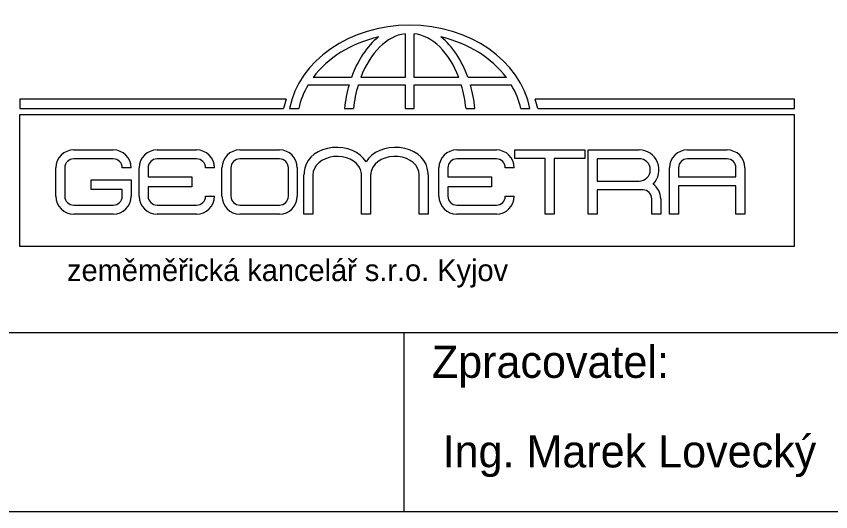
# Model space of a CAD drawing. Extents: x -558358 to -557517, y -1073785 to -1073189.
# Drawn here: x -557597.85 to -557552.36, y -1073682.09 to -1073654.43 of the extents above; entities that cross this region are included whole.
import ezdxf

# ---------------------------------------------------------------- set-up
doc = ezdxf.new("R2010")
doc.units = 0
doc.layers.add('Rozpiska_pole_6', color=7, linetype='Continuous')
doc.layers.add('ZZZ - Razítko', color=7, linetype='Continuous')

msp = doc.modelspace()

# ---------------------------------------------------------------- linework, layer by layer
at = {"layer": 'Rozpiska_pole_6'}
for p, q in [((-557706.534, -1073672.088), (-557536.534, -1073672.088)), ((-557576.184, -1073682.088), (-557576.184, -1073672.088))]:
    msp.add_line(p, q, dxfattribs=at)
msp.add_lwpolyline([(-557706.534, -1073632.088), (-557536.534, -1073632.088), (-557536.534, -1073682.088), (-557706.534, -1073682.088)], close=True, dxfattribs=at)
at = {"layer": 'ZZZ - Razítko'}
for p, q in [((-557576.139, -1073655.401), (-557576.139, -1073657.847)), ((-557575.632, -1073657.847), (-557575.632, -1073655.399)), ((-557579.132, -1073657.847), (-557581.277, -1073657.847)), ((-557576.139, -1073657.847), (-557578.615, -1073657.847)), ((-557573.137, -1073657.847), (-557575.632, -1073657.847)), ((-557570.475, -1073657.847), (-557572.62, -1073657.847)), ((-557581.552, -1073658.258), (-557579.265, -1073658.258)), ((-557578.755, -1073658.258), (-557576.139, -1073658.258)), ((-557576.139, -1073658.258), (-557576.139, -1073659.578)), ((-557575.632, -1073659.578), (-557575.632, -1073658.258)), ((-557575.632, -1073658.258), (-557572.998, -1073658.258)), ((-557572.488, -1073658.258), (-557570.2, -1073658.258)), ((-557582.783, -1073659.047), (-557597.663, -1073659.047)), ((-557597.663, -1073659.047), (-557597.663, -1073659.578)), ((-557554.385, -1073659.047), (-557568.863, -1073659.047)), ((-557554.385, -1073659.578), (-557554.385, -1073659.047)), ((-557597.663, -1073659.578), (-557582.921, -1073659.578)), ((-557582.595, -1073659.578), (-557582.078, -1073659.578)), ((-557579.522, -1073659.578), (-557579.022, -1073659.578)), ((-557576.139, -1073659.578), (-557575.632, -1073659.578)), ((-557572.731, -1073659.578), (-557572.23, -1073659.578)), ((-557569.674, -1073659.578), (-557569.157, -1073659.578)), ((-557568.725, -1073659.578), (-557554.385, -1073659.578)), ((-557554.387, -1073659.923), (-557597.67, -1073659.923)), ((-557597.67, -1073659.923), (-557597.67, -1073667.261)), ((-557554.387, -1073667.261), (-557554.387, -1073659.923)), ((-557594.645, -1073661.889), (-557592.434, -1073661.889)), ((-557589.989, -1073661.889), (-557587.778, -1073661.889)), ((-557585.365, -1073661.889), (-557583.154, -1073661.889)), ((-557573.246, -1073661.889), (-557571.036, -1073661.889)), ((-557565.909, -1073661.889), (-557563.064, -1073661.889)), ((-557560.361, -1073661.889), (-557558.15, -1073661.889)), ((-557592.434, -1073662.387), (-557594.645, -1073662.387)), ((-557587.778, -1073662.387), (-557589.989, -1073662.387)), ((-557583.154, -1073662.387), (-557585.365, -1073662.387)), ((-557571.036, -1073662.387), (-557573.246, -1073662.387)), ((-557568.303, -1073665.471), (-557568.303, -1073662.375)), ((-557567.8, -1073662.375), (-557567.8, -1073665.471)), ((-557563.064, -1073662.378), (-557565.405, -1073662.378)), ((-557565.405, -1073662.378), (-557565.405, -1073663.627)), ((-557558.15, -1073662.387), (-557560.361, -1073662.387)), ((-557595.643, -1073664.473), (-557595.643, -1073662.887)), ((-557595.144, -1073662.887), (-557595.144, -1073664.473)), ((-557591.437, -1073662.887), (-557591.935, -1073662.887)), ((-557590.986, -1073664.473), (-557590.986, -1073662.887)), ((-557590.488, -1073662.887), (-557590.488, -1073663.397)), ((-557586.78, -1073662.887), (-557587.279, -1073662.887)), ((-557586.363, -1073664.473), (-557586.363, -1073662.887)), ((-557585.864, -1073662.887), (-557585.864, -1073664.473)), ((-557582.655, -1073664.473), (-557582.655, -1073662.887)), ((-557582.156, -1073662.887), (-557582.156, -1073664.473)), ((-557574.244, -1073664.473), (-557574.244, -1073662.887)), ((-557573.745, -1073662.887), (-557573.745, -1073663.397)), ((-557570.038, -1073662.887), (-557570.536, -1073662.887)), ((-557561.359, -1073665.471), (-557561.359, -1073662.887)), ((-557560.86, -1073662.887), (-557560.86, -1073663.395)), ((-557557.651, -1073663.395), (-557557.651, -1073662.887)), ((-557557.152, -1073662.887), (-557557.152, -1073665.471)), ((-557581.784, -1073665.471), (-557581.784, -1073663.286)), ((-557581.283, -1073663.286), (-557581.283, -1073665.471)), ((-557578.564, -1073665.471), (-557578.564, -1073663.286)), ((-557578.063, -1073663.286), (-557578.063, -1073665.471)), ((-557575.345, -1073665.471), (-557575.345, -1073663.286)), ((-557574.844, -1073663.286), (-557574.844, -1073665.471)), ((-557593.67, -1073664.095), (-557593.67, -1073663.55)), ((-557593.67, -1073663.55), (-557591.437, -1073663.55)), ((-557591.437, -1073663.55), (-557591.437, -1073664.473)), ((-557590.488, -1073663.397), (-557588.045, -1073663.397)), ((-557588.045, -1073663.397), (-557588.045, -1073663.942)), ((-557573.745, -1073663.397), (-557571.302, -1073663.397)), ((-557571.302, -1073663.397), (-557571.302, -1073663.942)), ((-557565.405, -1073663.627), (-557563.064, -1073663.627)), ((-557560.86, -1073663.395), (-557557.651, -1073663.395)), ((-557591.935, -1073664.095), (-557593.67, -1073664.095)), ((-557591.935, -1073664.473), (-557591.935, -1073664.095)), ((-557588.045, -1073663.942), (-557590.488, -1073663.942)), ((-557590.488, -1073663.942), (-557590.488, -1073664.473)), ((-557571.302, -1073663.942), (-557573.745, -1073663.942)), ((-557573.745, -1073663.942), (-557573.745, -1073664.473)), ((-557563.064, -1073664.116), (-557565.405, -1073664.116)), ((-557562.85, -1073664.12), (-557563.064, -1073664.116)), ((-557557.651, -1073663.899), (-557560.86, -1073663.899)), ((-557560.86, -1073663.899), (-557560.86, -1073665.471)), ((-557557.651, -1073665.471), (-557557.651, -1073663.899)), ((-557587.279, -1073664.473), (-557586.78, -1073664.473)), ((-557570.536, -1073664.473), (-557570.038, -1073664.473)), ((-557562.351, -1073665.471), (-557562.351, -1073664.619)), ((-557561.853, -1073664.619), (-557561.853, -1073665.471)), ((-557594.645, -1073664.972), (-557592.434, -1073664.972)), ((-557589.989, -1073664.972), (-557587.778, -1073664.972)), ((-557585.365, -1073664.972), (-557583.154, -1073664.972)), ((-557573.246, -1073664.972), (-557571.036, -1073664.972)), ((-557592.434, -1073665.471), (-557594.645, -1073665.471)), ((-557587.778, -1073665.471), (-557589.989, -1073665.471)), ((-557583.154, -1073665.471), (-557585.365, -1073665.471)), ((-557581.283, -1073665.471), (-557581.784, -1073665.471)), ((-557578.063, -1073665.471), (-557578.564, -1073665.471)), ((-557574.844, -1073665.471), (-557575.345, -1073665.471)), ((-557571.036, -1073665.471), (-557573.246, -1073665.471)), ((-557567.8, -1073665.471), (-557568.303, -1073665.471)), ((-557561.853, -1073665.471), (-557562.351, -1073665.471)), ((-557560.86, -1073665.471), (-557561.359, -1073665.471)), ((-557557.152, -1073665.471), (-557557.651, -1073665.471)), ((-557597.67, -1073667.261), (-557554.387, -1073667.261))]:
    msp.add_line(p, q, dxfattribs=at)
for points in [[(-557568.303, -1073662.375), (-557570.001, -1073662.375), (-557570.001, -1073661.889), (-557566.087, -1073661.889)], [(-557566.087, -1073661.889), (-557566.087, -1073662.375), (-557567.8, -1073662.375)], [(-557565.405, -1073664.116), (-557565.405, -1073665.471), (-557565.909, -1073665.471), (-557565.909, -1073661.889)]]:
    msp.add_lwpolyline(points, dxfattribs=at)
for centre, radius, start, end in [((-557594.645, -1073662.887), 0.998, 90, 180), ((-557592.434, -1073662.887), 0.998, 360, 90), ((-557589.989, -1073662.887), 0.998, 90, 180), ((-557587.778, -1073662.887), 0.998, 360, 90), ((-557585.365, -1073662.887), 0.998, 90, 180), ((-557583.154, -1073662.887), 0.998, 360, 90), ((-557573.246, -1073662.887), 0.998, 90, 180), ((-557571.036, -1073662.887), 0.998, 360, 90), ((-557563.064, -1073663.003), 1.114, 314.4573, 90), ((-557560.361, -1073662.887), 0.998, 90, 180), ((-557558.15, -1073662.887), 0.998, 360, 90), ((-557594.645, -1073662.887), 0.499, 90, 180), ((-557592.434, -1073662.887), 0.499, 0, 90), ((-557589.989, -1073662.887), 0.499, 90, 180), ((-557587.778, -1073662.887), 0.499, 0, 90), ((-557585.365, -1073662.887), 0.499, 90, 180), ((-557583.154, -1073662.887), 0.499, 0, 90), ((-557573.246, -1073662.887), 0.499, 90, 180), ((-557571.036, -1073662.887), 0.499, 0, 90), ((-557563.064, -1073663.003), 0.625, 270, 90), ((-557560.361, -1073662.887), 0.499, 90, 180), ((-557558.15, -1073662.887), 0.499, 0, 90), ((-557579.846, -1073663.336), 1.938, 166.9658, 178.5209), ((-557576.782, -1073663.336), 1.938, 1.4791, 13.0342), ((-557579.518, -1073663.35), 0.957, 3.8649, 22.4157), ((-557576.831, -1073663.408), 1.238, 162.6139, 174.3506), ((-557562.85, -1073664.619), 0.998, 360, 55.4473), ((-557562.85, -1073664.619), 0.499, 0, 90), ((-557594.645, -1073664.473), 0.998, 180, 270), ((-557594.645, -1073664.473), 0.499, 180, 270), ((-557592.434, -1073664.473), 0.998, 270, 0), ((-557592.434, -1073664.473), 0.499, 270, 0), ((-557589.989, -1073664.473), 0.998, 180, 270), ((-557589.989, -1073664.473), 0.499, 180, 270), ((-557587.778, -1073664.473), 0.998, 270, 0), ((-557587.778, -1073664.473), 0.499, 270, 0), ((-557585.365, -1073664.473), 0.998, 180, 270), ((-557585.365, -1073664.473), 0.499, 180, 270), ((-557583.154, -1073664.473), 0.998, 270, 0), ((-557583.154, -1073664.473), 0.499, 270, 0), ((-557573.246, -1073664.473), 0.998, 180, 270), ((-557573.246, -1073664.473), 0.499, 180, 270), ((-557571.036, -1073664.473), 0.998, 270, 0), ((-557571.036, -1073664.473), 0.499, 270, 0)]:
    msp.add_arc(centre, radius, start, end, dxfattribs=at)
for centre, major_axis, ratio, start_param, end_param in [((-557575.876, -1073660.451), (-6.804, 0), 0.811768, 3.300239, 6.124539), ((-557575.876, -1073660.451), (-6.296, 0), 0.804826, 4.992897, 5.743383), ((-557575.876, -1073660.451), (0, 5.524), 0.668443, 0.491666, 1.079789), ((-557575.876, -1073660.451), (0, 5.067), 0.630136, 0.08224, 1.030995), ((-557575.876, -1073660.451), (0, 5.067), 0.630136, 5.252191, 6.206521), ((-557575.876, -1073660.451), (0, 5.524), 0.668443, 5.203397, 5.79152), ((-557575.876, -1073660.451), (-6.296, 0), 0.804826, 3.681394, 4.431881), ((-557575.876, -1073660.451), (-6.296, 0), 0.804826, 5.835664, 6.110118), ((-557575.876, -1073660.451), (0, 5.524), 0.668443, 1.16256, 1.41215), ((-557575.876, -1073660.451), (0, 5.067), 0.630136, 1.123275, 1.397729), ((-557575.876, -1073660.451), (0, 5.067), 0.630136, 4.885456, 5.159911), ((-557575.876, -1073660.451), (0, 5.524), 0.668443, 4.871035, 5.120625), ((-557575.876, -1073660.451), (-6.296, 0), 0.804826, 3.31466, 3.589114), ((-557576.202, -1073660.451), (-6.804, 0), 0.811768, 6.026233, 6.124539), ((-557575.444, -1073660.451), (-6.804, 0), 0.811768, 3.300239, 3.398545), ((-557579.955, -1073663.13), (1.805, 0), 0.766187, 0.429647, 2.97338), ((-557576.673, -1073663.13), (-1.805, 0), 0.766187, 3.309805, 5.853538), ((-557579.93, -1073663.286), (1.354, 0), 0.766187, 0.29376, 3.141593), ((-557576.698, -1073663.286), (-1.354, 0), 0.766187, 3.141593, 6.041607)]:
    msp.add_ellipse(centre, major_axis=major_axis, ratio=ratio, start_param=start_param, end_param=end_param, dxfattribs=at)

# ---------------------------------------------------------------- texts
at = {"layer": 'Rozpiska_pole_6'}
for s, p in [('Zpracovatel:', (-557574.638, -1073674.615)), ('Ing. Marek Lovecký', (-557574.037, -1073679.615))]:
    msp.add_text(s, height=1.8, dxfattribs=at).set_placement(p)
at = {"layer": 'ZZZ - Razítko'}
msp.add_text('zeměměřická kancelář s.r.o. Kyjov', height=1.20984, dxfattribs=at).set_placement((-557595.018, -1073669.21))

doc.saveas('drawing.dxf')
